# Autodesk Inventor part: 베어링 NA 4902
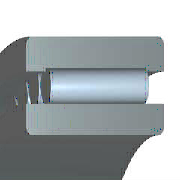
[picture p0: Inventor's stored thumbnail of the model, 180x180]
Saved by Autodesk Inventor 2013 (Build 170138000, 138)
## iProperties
IsCustomPart: 1
Created: 2012-02
Part Number: 베어링 NA 4902
Material: 강철, 연강
Description: 니들 롤러 베어링 - 경계 치수 및 공차
Document SubType Name: Modeling
Standard: KS B 2029
Designer: mduedu
Standards Organization: KS
Language: ko-KR
Size Designation: NA 4902 - 15 x 28 x 13
Categories: <MemberInstance><Categories><Category DisplayName="샤프트 부품" InternalName="7f7aeb1f-a693-4053-b835-cee3144e0d98" Mnemonic="SHFT"><Category DisplayName="베어링" Inter
Density: 7.86 g/cm^3
Mass: 37.7482 g
Surface Area: 52.7153 cm^2
Volume: 4.80257 cm^3
Author: mduedu
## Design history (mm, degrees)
sketch "스케치"
  geometry: L1 (1.857, 11.5)-(11.143, 11.5); L2 (11.143, 11.5)-(11.143, 10); L3 (13, 10)-(0, 10); L4 (1.857, 10)-(1.857, 11.5); L5 (1.857, 10.75)-(11.143, 10.75); L6 (6.5, 10.75)-(6.5, 10); L7 (0, 7.5)-(13, 7.5); L8 (0, 14)-(13, 14); L9 (13, 7.5)-(13, 10); L10 (13, 11.35)-(13, 14); L11 (1.857, 11.35)-(0, 11.35); L12 (11.143, 11.35)-(13, 11.35); L13 (-6, 0)-(36, 0) reference; L14 (0, -1.9)-(0, 14.9) reference
  constraints: 24 end point, 8 point on line, 3 midpoint, 3 parallel, 3 perpendicular, 2 symmetric about line, 1 horizontal, 1 other
  dimensions: "d6" = 15 diameter of L7 L13 (= WD); "d7" = 20 diameter of L3 L13 (= KID1); "d8" = 28 diameter of L8 L13 (= BD); "d9" = 21.5 diameter of L6.start L13 (= 0.5 x WD + 0.5 x BD); "d10" = 22.7 diameter of L12 L13 (= 0.9 x BD + 0.9 x WD - 0.8 x KID1); "d11" = 23 diameter of L1 L13 (= BD + WD - KID1); "d12" = 1.85714 distance between parallel lines of L14 L4 (= 0.142857 x KB); "d13" = 13 distance between parallel lines of L14 L9 (= KB); "d14" = 11.14286 distance between parallel lines of L14 L2 (= 0.857143 x KB)
revolve "본체" stored, may be unused: angle "d17" = 90 deg
revolve "롤러" stored, may be unused: angle "d18" = 90 deg
node "작업 평면1"
body "Solid1"
fillet "모깎기1" dims "d0" = 0.3 (= KRS)
pattern_circular "IDS_ARRAYROLLER[SIMPL:T]" dims angle "d2" = 360 deg
other parameters: "WD" = 15 [user parameter; used in 6 equation terms], "BD" = 28 [user parameter; used in 6 equation terms], "KB" = 13 [user parameter; used in 3 equation terms], "KID1" = 20 [user parameter; used in 4 equation terms], "KRS" = 0.3 [user parameter; used in 1 equation term], "d3" = 0, "d4" = 0, "d5" = 0, "d15" = 0, "d16" = 0, "BC0" = 1.37e+07 [user parameter], "WR" = 7.5 (= 0.5 x WD) [user parameter], "BBA" = 0 [user parameter], "BC" = 1.02e+07 [user parameter], "BR" = 14 (= 0.5 x BD) [user parameter]
